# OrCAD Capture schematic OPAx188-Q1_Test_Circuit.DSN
size A; title: OPAx188-Q1 Precision, Low-Noise, Rail-to-Rail Output, 36-V; rev: 1.5; note: Datasheet: SBOS860  EVM: N/A
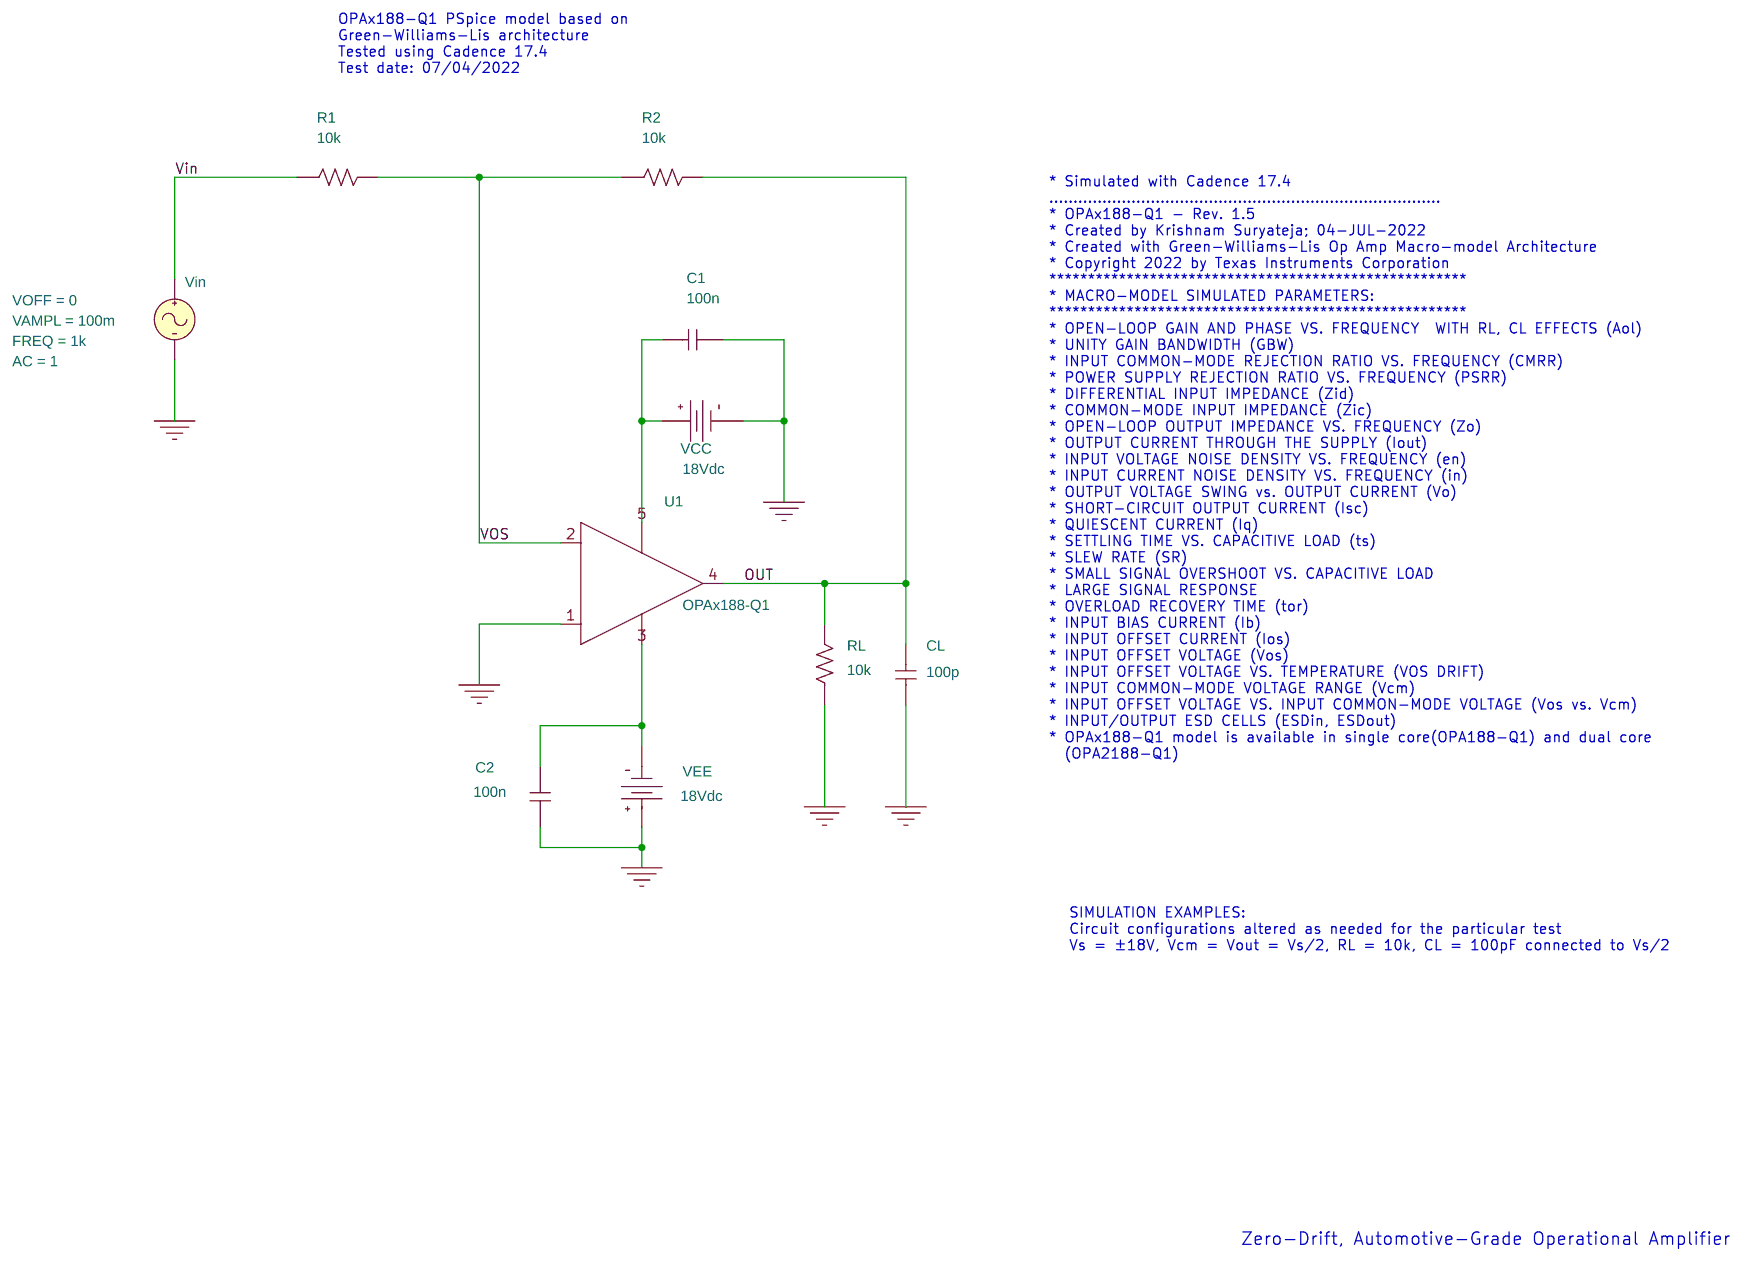
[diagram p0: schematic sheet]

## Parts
C1  100n  [cap196]
C2  100n  [cap196]
CL  100p  [cap196]
R1  10k  [AXRC05]
R2  10k  [AXRC05]
RL  10k  [AXRC05]
U1  OPAx188-Q1
VCC  VDC
VEE  VDC
Vin  VSIN

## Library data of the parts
C1 C2 CL = C
R1 R2 RL = R
U1 = OPAx188-Q1
VCC VEE = VDC: DC: 18Vdc
Vin = VSIN: AC: 1; FREQ: 1k; VAMPL: 100m; VOFF: 0

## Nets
Vin: R1.1 Vin.1(+)
0: C1.2 C2.1 CL.2 RL.1 U1.1(+) VCC.1(-) VEE.0(+) Vin.2(-)
OUT: CL.1 R2.2 RL.2 U1.4(OUT)
VOS: R1.2 R2.1 U1.2(-)
N27303: C1.1 U1.5(V+) VCC.0(+)
N27354: C2.2 U1.3(V-) VEE.1(-)

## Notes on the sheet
- OPAx188-Q1 PSpice model based on
  Green-Williams-Lis architecture
  Tested using Cadence 17.4
  Test date: 07/04/2022
- * Simulated with Cadence 17.4
  .................................................................................
  * OPAx188-Q1 - Rev. 1.5
  * Created by Krishnam Suryateja; 04-JUL-2022
  * Created with Green-Williams-Lis Op Amp Macro-model Architecture
  * Copyright 2022 by Texas Instruments Corporation
  ******************************************************
  * MACRO-MODEL SIMULATED PARAMETERS:
  ******************************************************
  * OPEN-LOOP GAIN AND PHASE VS. FREQUENCY  WITH RL, CL EFFECTS (Aol)
  * UNITY GAIN BANDWIDTH (GBW)
  * INPUT COMMON-MODE REJECTION RATIO VS. FREQUENCY (CMRR)
  * POWER SUPPLY REJECTION RATIO VS. FREQUENCY (PSRR)
  * DIFFERENTIAL INPUT IMPEDANCE (Zid)
  * COMMON-MODE INPUT IMPEDANCE (Zic)
  * OPEN-LOOP OUTPUT IMPEDANCE VS. FREQUENCY (Zo)
  * OUTPUT CURRENT THROUGH THE SUPPLY (Iout)
  * INPUT VOLTAGE NOISE DENSITY VS. FREQUENCY (en)
  * INPUT CURRENT NOISE DENSITY VS. FREQUENCY (in)
  * OUTPUT VOLTAGE SWING vs. OUTPUT CURRENT (Vo)
  * SHORT-CIRCUIT OUTPUT CURRENT (Isc)
  * QUIESCENT CURRENT (Iq)
  * SETTLING TIME VS. CAPACITIVE LOAD (ts)
  * SLEW RATE (SR)
  * SMALL SIGNAL OVERSHOOT VS. CAPACITIVE LOAD
  * LARGE SIGNAL RESPONSE
  * OVERLOAD RECOVERY TIME (tor)
  * INPUT BIAS CURRENT (Ib)
  * INPUT OFFSET CURRENT (Ios)
  * INPUT OFFSET VOLTAGE (Vos)
  * INPUT OFFSET VOLTAGE VS. TEMPERATURE (VOS DRIFT)
  * INPUT COMMON-MODE VOLTAGE RANGE (Vcm)
  * INPUT OFFSET VOLTAGE VS. INPUT COMMON-MODE VOLTAGE (Vos vs. Vcm)
  * INPUT/OUTPUT ESD CELLS (ESDin, ESDout)
  * OPAx188-Q1 model is available in single core(OPA188-Q1) and dual core
    (OPA2188-Q1)
- SIMULATION EXAMPLES:
  Circuit configurations altered as needed for the particular test
  Vs = ±18V, Vcm = Vout = Vs/2, RL = 10k, CL = 100pF connected to Vs/2
- Zero-Drift, Automotive-Grade Operational Amplifier
